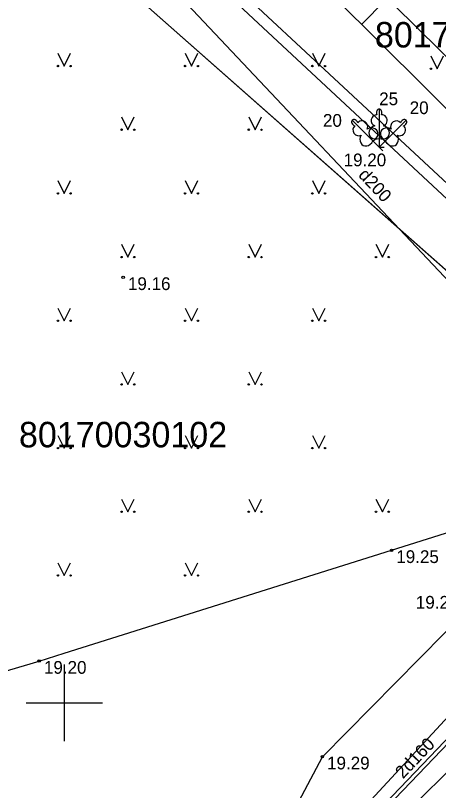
# Model space of a CAD drawing. Extents: x 532933 to 533143, y 328014 to 328163.
# Drawn here: x 532998.08 to 533014.71, y 328096.56 to 328126.98 of the extents above; entities that cross this region are included whole.
import ezdxf

# ---------------------------------------------------------------- set-up
doc = ezdxf.new("R2010")
doc.units = 0
for name, color, linetype in [('APGR_SARK_####_####_#', 7, 'Continuous'), ('CELI_CMAL_####_####_#', 7, 'Continuous'), ('CELI_SEGL_####_####_#', 7, 'Continuous'), ('ELEK_ACRL_####_####_#', 7, 'Continuous'), ('ELEK_ACRL_####_TKST_#', 7, 'Continuous'), ('ELEK_VADP_VSPR_####_I', 7, 'Continuous'), ('GEOD_ELEM_####_####_#', 7, 'Continuous'), ('RELJ_AATZ_####_TKST_#', 7, 'Continuous'), ('RELJ_ELEM_####_####_#', 7, 'Continuous'), ('ROBZ_PROJ_####_####_#', 7, 'Continuous'), ('ROBZ_PROJ_####_TKST_#', 7, 'Continuous'), ('ROBZ_UZMR_####_####_#', 7, 'Continuous'), ('ROBZ_UZMR_####_TKST_#', 7, 'Continuous'), ('SAKK_IZVK_####_TKST_#', 7, 'Continuous'), ('SAKK_KKAN_####_####_#', 7, 'Continuous'), ('SILT_VADP_UDEN_####_#', 7, 'Continuous'), ('SKAN_VADP_PAST_####_#', 7, 'Continuous'), ('SKAN_VADP_PAST_TKST_#', 7, 'Continuous'), ('TERT_DIAM_####_TKST_#', 7, 'Continuous'), ('TERT_ELEM_####_####_#', 7, 'Continuous')]:
    doc.layers.add(name, color=color, linetype=linetype)

msp = doc.modelspace()

# ---------------------------------------------------------------- linework, layer by layer
at = {"layer": 'APGR_SARK_####_####_#'}
msp.add_line((533025.763, 328107.492), (532984.275, 328144.093), dxfattribs=at)
at = {"layer": 'CELI_CMAL_####_####_#'}
msp.add_line((533019.246, 328101.385), (533013.532, 328095.798), dxfattribs=at)
for points in [[(533000, 328140.228), (533009.371, 328130.936), (533020.128, 328120.334), (533028.429, 328112.049)], [(533012.863, 328105.989), (533027.507, 328110.598)], [(533000, 328101.952), (533012.863, 328105.989)], [(532960.996, 328082.718), (532967.7, 328088.991), (532974.969, 328093.406), (532984.293, 328097.298), (532999.014, 328101.642), (533000, 328101.952)]]:
    msp.add_lwpolyline(points, dxfattribs=at)
at = {"layer": 'CELI_SEGL_####_####_#'}
msp.add_lwpolyline([(533011.521, 328092.239), (533007.24, 328084.661), (533003.535, 328084.875), (533003.518, 328086.539), (533005.617, 328089.34), (533010.142, 328097.887), (533015.888, 328103.687), (533020.601, 328107.151)], dxfattribs=at)
at = {"layer": 'ELEK_ACRL_####_####_#'}
for points in [[(533013.203, 328096.663), (533020.765, 328104.555)], [(533013.311, 328096.559), (533020.873, 328104.451)], [(533002.47, 328085.498), (533013.203, 328096.663)]]:
    msp.add_lwpolyline(points, dxfattribs=at)
at = {"layer": 'ELEK_VADP_VSPR_####_I'}
for points in [[(533000, 328082.63), (533000.322, 328083.149), (533002.47, 328085.498), (533013.203, 328096.663), (533020.765, 328104.555), (533025.03, 328108.829)], [(533000, 328082.346), (533000.442, 328083.058), (533002.579, 328085.395), (533013.311, 328096.559), (533020.872, 328104.45), (533025.042, 328108.629)]]:
    msp.add_lwpolyline(points, dxfattribs=at)
at = {"layer": 'GEOD_ELEM_####_####_#'}
for p, q in [((533000, 328101.5), (533000, 328100)), ((532998.5, 328100), (533000, 328100)), ((533000, 328100), (533000, 328098.5)), ((533000, 328100), (533001.5, 328100))]:
    msp.add_line(p, q, dxfattribs=at)
at = {"layer": 'RELJ_ELEM_####_####_#'}
for centre in [(533002.315, 328116.705), (533012.863, 328105.989), (532999.014, 328101.642), (533010.142, 328097.887)]:
    msp.add_circle(centre, 0.05, dxfattribs=at)
at = {"layer": 'ROBZ_PROJ_####_####_#'}
msp.add_line((533025.763, 328107.492), (532984.275, 328144.093), dxfattribs=at)
at = {"layer": 'ROBZ_UZMR_####_####_#'}
msp.add_line((532984.275, 328144.093), (533025.763, 328107.492), dxfattribs=at)
at = {"layer": 'SAKK_IZVK_####_TKST_#'}
msp.add_line((533011.691, 328126.639), (533012.612, 328127.567), dxfattribs=at)
at = {"layer": 'SAKK_KKAN_####_####_#'}
msp.add_line((533026.568, 328111.881), (532996.716, 328079.621), dxfattribs=at)
msp.add_lwpolyline([(533000, 328138.237), (533026.568, 328111.881), (533036.477, 328102.895)], dxfattribs=at)
at = {"layer": 'SILT_VADP_UDEN_####_#'}
for points in [[(533004.853, 328045.947), (533019.384, 328034.966), (533019.749, 328035.185), (533031.003, 328047.839), (533031.356, 328048.225), (533031.335, 328048.654), (533025.793, 328053.779), (533025.755, 328054.215), (533035.838, 328064.377), (533036.105, 328064.808), (533033.176, 328075.216), (533032.836, 328076.021), (533015.446, 328091.145), (533015.462, 328091.585), (533029.065, 328106.172), (533029.033, 328106.692), (533017.302, 328118.3), (533000, 328134.38)], [(533000, 328133.784), (533016.764, 328118.182), (533028.476, 328106.559), (533028.508, 328106.039), (533014.85, 328091.596), (533014.892, 328091.077), (533032.527, 328075.724), (533032.689, 328075.239), (533035.542, 328065.283), (533035.311, 328064.711), (533024.98, 328054.226), (533025.028, 328053.821), (533027.938, 328051.227), (533030.653, 328048.689), (533030.642, 328048.162), (533019.754, 328035.526), (533019.215, 328035.483), (533005.473, 328047.022)]]:
    msp.add_lwpolyline(points, dxfattribs=at)
at = {"layer": 'SKAN_VADP_PAST_####_#'}
msp.add_lwpolyline([(533001.531, 328130.94), (533018.885, 328112.548), (533025.52, 328119.937), (533007.233, 328137.297), (533000, 328145.658)], dxfattribs=at)
at = {"layer": 'TERT_ELEM_####_####_#'}
for p, q in [((532999.75, 328125.5), (533000, 328125)), ((533000, 328125), (533000.25, 328125.5)), ((533004.75, 328125.5), (533005, 328125)), ((533005, 328125), (533005.25, 328125.5)), ((533009.75, 328125.5), (533010, 328125)), ((533010, 328125), (533010.25, 328125.5)), ((533014.408, 328125.394), (533014.658, 328124.894)), ((533014.658, 328124.894), (533014.908, 328125.394)), ((533002.25, 328123), (533002.5, 328122.5)), ((533002.5, 328122.5), (533002.75, 328123)), ((533007.25, 328123), (533007.5, 328122.5)), ((533007.5, 328122.5), (533007.75, 328123)), ((533012.13, 328122.058), (533012.376, 328121.812)), ((533012.376, 328122.159), (533012.376, 328121.812)), ((533012.621, 328122.058), (533012.376, 328121.812)), ((533012.376, 328121.812), (533012.517, 328121.954)), ((533012.376, 328121.812), (533012.576, 328121.812)), ((533012.376, 328121.812), (533012.517, 328121.671)), ((532999.75, 328120.5), (533000, 328120)), ((533000, 328120), (533000.25, 328120.5)), ((533004.75, 328120.5), (533005, 328120)), ((533005, 328120), (533005.25, 328120.5)), ((533009.75, 328120.5), (533010, 328120)), ((533010, 328120), (533010.25, 328120.5)), ((533002.25, 328118), (533002.5, 328117.5)), ((533002.5, 328117.5), (533002.75, 328118)), ((533007.25, 328118), (533007.5, 328117.5)), ((533007.5, 328117.5), (533007.75, 328118)), ((533012.25, 328118), (533012.5, 328117.5)), ((533012.5, 328117.5), (533012.75, 328118)), ((532999.75, 328115.5), (533000, 328115)), ((533000, 328115), (533000.25, 328115.5)), ((533004.75, 328115.5), (533005, 328115)), ((533005, 328115), (533005.25, 328115.5)), ((533009.75, 328115.5), (533010, 328115)), ((533010, 328115), (533010.25, 328115.5)), ((533002.25, 328113), (533002.5, 328112.5)), ((533002.5, 328112.5), (533002.75, 328113)), ((533007.25, 328113), (533007.5, 328112.5)), ((533007.5, 328112.5), (533007.75, 328113)), ((532999.75, 328110.5), (533000, 328110)), ((533000, 328110), (533000.25, 328110.5)), ((533004.75, 328110.5), (533005, 328110)), ((533005, 328110), (533005.25, 328110.5)), ((533009.75, 328110.5), (533010, 328110)), ((533010, 328110), (533010.25, 328110.5)), ((533002.25, 328108), (533002.5, 328107.5)), ((533002.5, 328107.5), (533002.75, 328108)), ((533007.25, 328108), (533007.5, 328107.5)), ((533007.5, 328107.5), (533007.75, 328108)), ((533012.25, 328108), (533012.5, 328107.5)), ((533012.5, 328107.5), (533012.75, 328108)), ((532999.75, 328105.5), (533000, 328105)), ((533000, 328105), (533000.25, 328105.5)), ((533004.75, 328105.5), (533005, 328105)), ((533005, 328105), (533005.25, 328105.5))]:
    msp.add_line(p, q, dxfattribs=at)
for points in [[(533012.376, 328123.312), (533012.376, 328122.159)], [(533012.465, 328123.08), (533012.464, 328123.081)], [(533011.315, 328122.873), (533012.13, 328122.058)], [(533011.542, 328122.772), (533011.541, 328122.772)], [(533013.436, 328122.873), (533012.621, 328122.058)], [(533013.335, 328122.645), (533013.335, 328122.647)]]:
    msp.add_lwpolyline(points, dxfattribs=at)
for centre, radius in [((532999.75, 328125), 0.028), ((533000.25, 328125), 0.0263), ((533004.75, 328125), 0.028), ((533005.25, 328125), 0.0263), ((533009.75, 328125), 0.028), ((533010.25, 328125), 0.0263), ((533014.408, 328124.894), 0.028), ((533002.25, 328122.5), 0.028), ((533002.75, 328122.5), 0.0263), ((533007.25, 328122.5), 0.028), ((533007.75, 328122.5), 0.0263), ((532999.75, 328120), 0.028), ((533000.25, 328120), 0.0263), ((533004.75, 328120), 0.028), ((533005.25, 328120), 0.0263), ((533009.75, 328120), 0.028), ((533010.25, 328120), 0.0263), ((533002.25, 328117.5), 0.028), ((533002.75, 328117.5), 0.0263), ((533007.25, 328117.5), 0.028), ((533007.75, 328117.5), 0.0263), ((533012.25, 328117.5), 0.028), ((533012.75, 328117.5), 0.0263), ((532999.75, 328115), 0.028), ((533000.25, 328115), 0.0263), ((533004.75, 328115), 0.028), ((533005.25, 328115), 0.0263), ((533009.75, 328115), 0.028), ((533010.25, 328115), 0.0263), ((533002.25, 328112.5), 0.028), ((533002.75, 328112.5), 0.0263), ((533007.25, 328112.5), 0.028), ((533007.75, 328112.5), 0.0263), ((532999.75, 328110), 0.028), ((533000.25, 328110), 0.0263), ((533004.75, 328110), 0.028), ((533005.25, 328110), 0.0263), ((533009.75, 328110), 0.028), ((533010.25, 328110), 0.0263), ((533002.25, 328107.5), 0.028), ((533002.75, 328107.5), 0.0263), ((533007.25, 328107.5), 0.028), ((533007.75, 328107.5), 0.0263), ((533012.25, 328107.5), 0.028), ((533012.75, 328107.5), 0.0263), ((532999.75, 328105), 0.028), ((533000.25, 328105), 0.0263), ((533004.75, 328105), 0.028), ((533005.25, 328105), 0.0263)]:
    msp.add_circle(centre, radius, dxfattribs=at)
for centre, major_axis, ratio, start_param, end_param in [((533012.376, 328123.162), (0, -0.15), 0.707107, 3.14537, 5.287485), ((533012.375, 328123.162), (0, -0.15), 0.707107, 0.995701, 3.137816), ((533011.421, 328122.767), (0.106, -0.106), 0.707107, 0.995701, 3.137816), ((533012.247, 328122.868), (-0.039, -0.212), 0.861323, 3.141593, 6.283185), ((533012.504, 328122.868), (0.039, -0.212), 0.861323, 0, 3.141593), ((533013.33, 328122.767), (-0.106, -0.106), 0.707107, 3.14537, 5.287485), ((533011.421, 328122.767), (0.106, -0.106), 0.707107, 3.14537, 5.287485), ((533011.539, 328122.468), (0.123, -0.178), 0.861323, 3.141593, 6.283185), ((533011.72, 328122.649), (0.178, -0.123), 0.861323, 0, 3.141593), ((533012.286, 328122.405), (0.307, 0.095), 0.814445, 1.570796, 4.752015), ((533012.465, 328122.405), (-0.307, 0.095), 0.814445, 1.531171, 4.712389), ((533013.031, 328122.649), (-0.178, -0.123), 0.861323, 3.141593, 6.283185), ((533013.212, 328122.468), (-0.123, -0.178), 0.861323, 0, 3.141593), ((533013.33, 328122.767), (-0.106, -0.106), 0.707107, 0.995701, 3.137816), ((533011.893, 328122.168), (0.15, 0.284), 0.814445, 1.570796, 4.752015), ((533012.02, 328122.295), (-0.284, -0.15), 0.814445, 1.531171, 4.712389), ((533012.731, 328122.295), (0.284, -0.15), 0.814445, 1.570796, 4.752015), ((533012.858, 328122.168), (-0.15, 0.284), 0.814445, 1.531171, 4.712389)]:
    msp.add_ellipse(centre, major_axis=major_axis, ratio=ratio, start_param=start_param, end_param=end_param, dxfattribs=at)

# ---------------------------------------------------------------- texts
at = {"layer": 'ELEK_ACRL_####_TKST_#'}
msp.add_text('2d160', height=0.5, rotation=46.2233, dxfattribs=at).set_placement((533013.313, 328096.995))
at = {"layer": 'RELJ_AATZ_####_TKST_#'}
for s, p in [(' 19.20', (533010.793, 328121.063)), (' 19.16', (533002.315, 328116.205)), (' 19.25', (533012.863, 328105.489)), (' 19.23', (533013.631, 328103.697)), (' 19.20', (532999.014, 328101.142)), (' 19.29', (533010.142, 328097.387))]:
    msp.add_text(s, height=0.5, dxfattribs=at).set_placement(p)
at = {"layer": 'ROBZ_PROJ_####_TKST_#'}
msp.add_text('80170010170', height=1, dxfattribs=at).set_placement((533012.208, 328125.727))
at = {"layer": 'ROBZ_UZMR_####_TKST_#'}
msp.add_text('80170030102', height=1, dxfattribs=at).set_placement((532998.219, 328110.031))
at = {"layer": 'SKAN_VADP_PAST_TKST_#'}
msp.add_text('d200', height=0.5, rotation=313.1117, dxfattribs=at).set_placement((533011.526, 328120.695))
at = {"layer": 'TERT_DIAM_####_TKST_#'}
for s, p in [('25', (533012.376, 328123.462)), ('20', (533013.575, 328123.112)), ('20', (533010.166, 328122.615))]:
    msp.add_text(s, height=0.5, dxfattribs=at).set_placement(p)

doc.saveas('drawing.dxf')
